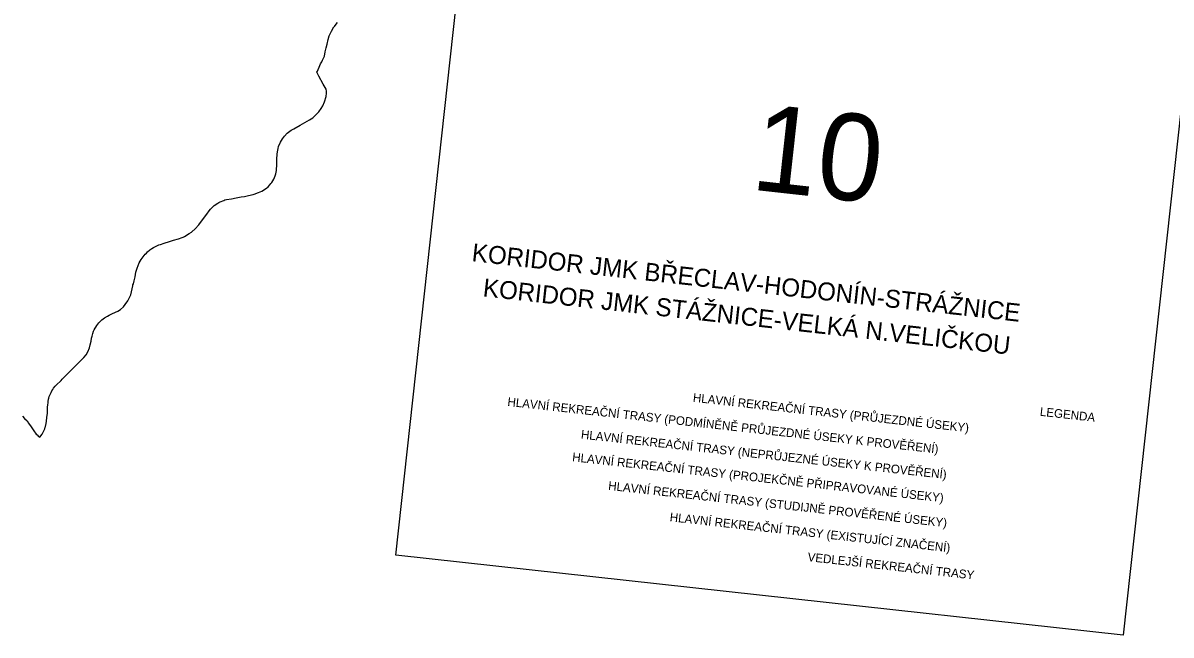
# Model space of a CAD drawing. Extents: x -678204 to -526855, y -1228851 to -1110393.
# Drawn here: x -574848 to -543059, y -1222170 to -1205218 of the extents above; entities that cross this region are included whole.
import ezdxf

# ---------------------------------------------------------------- set-up
doc = ezdxf.new("R2010")
doc.units = 0
for name, color, linetype in [('00_n_cyklo studie rekreacni hlavni', 7, 'Continuous'), ('00_n_cyklo trasovani rekreacni hlavni', 7, 'Continuous'), ('00_n_legenda popisy', 7, 'Continuous'), ('00_n_legenda popisy_hlavni', 7, 'Continuous'), ('_HELP BIG', 7, 'Continuous')]:
    doc.layers.add(name, color=color, linetype=linetype)

msp = doc.modelspace()

# ---------------------------------------------------------------- linework, layer by layer
at = {"layer": '00_n_cyklo studie rekreacni hlavni'}
for points in [[(-570414, -1211149), (-570379, -1211132), (-570249, -1211053), (-570181, -1211011), (-570068, -1210909), (-569987, -1210822), (-569975, -1210806), (-569934, -1210746), (-569868, -1210658), (-569817, -1210592), (-569761, -1210510), (-569696, -1210424), (-569656, -1210375), (-569575, -1210295), (-569550, -1210275), (-569454, -1210208), (-569427, -1210192), (-569384, -1210170), (-569287, -1210131), (-569256, -1210120), (-569211, -1210110), (-569076, -1210085), (-568947, -1210060), (-568802, -1210036), (-568711, -1210021), (-568637, -1210005), (-568518, -1209978), (-568471, -1209965), (-568448, -1209958), (-568322, -1209913), (-568233, -1209873), (-568106, -1209792), (-568059, -1209754), (-568008, -1209704), (-567985, -1209668), (-567959, -1209639), (-567901, -1209544), (-567861, -1209449), (-567846, -1209396), (-567829, -1209306), (-567819, -1209127), (-567814, -1208990), (-567807, -1208854), (-567801, -1208787), (-567786, -1208696), (-567770, -1208643), (-567718, -1208523), (-567665, -1208431), (-567602, -1208349), (-567528, -1208272), (-567420, -1208189), (-567349, -1208146), (-567175, -1208053), (-566910, -1207904), (-566824, -1207844), (-566744, -1207774), (-566657, -1207677), (-566593, -1207589), (-566549, -1207510), (-566499, -1207402), (-566457, -1207256), (-566441, -1207158), (-566440, -1207105), (-566457, -1207051), (-566533, -1206912), (-566652, -1206692), (-566709, -1206585), (-566693, -1206550), (-566632, -1206393), (-566612, -1206350), (-566574, -1206296), (-566551, -1206245), (-566503, -1206142), (-566478, -1206014), (-566454, -1205910), (-566427, -1205801), (-566395, -1205679), (-566370, -1205575), (-566355, -1205540), (-566303, -1205447), (-566243, -1205326)], [(-566151, -1205202), (-566243, -1205326)], [(-573761, -1215083), (-573705, -1215027), (-573631, -1214953), (-573484, -1214806), (-573344, -1214665), (-573267, -1214589), (-573163, -1214485), (-573098, -1214408), (-573048, -1214324), (-573005, -1214218), (-572983, -1214133), (-572964, -1214034), (-572946, -1213948), (-572931, -1213889), (-572913, -1213816), (-572891, -1213753), (-572874, -1213716), (-572805, -1213601), (-572743, -1213520), (-572663, -1213440), (-572586, -1213383), (-572508, -1213334), (-572460, -1213311), (-572371, -1213268), (-572223, -1213198), (-572145, -1213152), (-572060, -1213080), (-571972, -1212950), (-571964, -1212940), (-571947, -1212913), (-571905, -1212842), (-571863, -1212743), (-571845, -1212668), (-571828, -1212585), (-571809, -1212496), (-571805, -1212473), (-571786, -1212447), (-571765, -1212360), (-571744, -1212248), (-571720, -1212119), (-571690, -1212012), (-571661, -1211933), (-571628, -1211865), (-571575, -1211768), (-571464, -1211624), (-571429, -1211589), (-571396, -1211557), (-571332, -1211504), (-571277, -1211464), (-571233, -1211437), (-571158, -1211397), (-571086, -1211363), (-571044, -1211349), (-570938, -1211316), (-570790, -1211269), (-570681, -1211236), (-570541, -1211193), (-570444, -1211162), (-570414, -1211149)], [(-574862, -1216105), (-574808, -1216169), (-574734, -1216239), (-574692, -1216305), (-574622, -1216406), (-574548, -1216518), (-574485, -1216602), (-574453, -1216629), (-574422, -1216667), (-574385, -1216689), (-574320, -1216606), (-574266, -1216511), (-574246, -1216460), (-574230, -1216417), (-574223, -1216390), (-574204, -1216309), (-574198, -1216247), (-574186, -1216143), (-574173, -1216026), (-574170, -1215962), (-574164, -1215862), (-574159, -1215796), (-574154, -1215737), (-574149, -1215699), (-574140, -1215640), (-574132, -1215608), (-574118, -1215565), (-574095, -1215505), (-574069, -1215448), (-574047, -1215407), (-574022, -1215368), (-573998, -1215333), (-573956, -1215281), (-573930, -1215253), (-573794, -1215116), (-573761, -1215083)]]:
    msp.add_lwpolyline(points, dxfattribs=at)
at = {"layer": '00_n_cyklo trasovani rekreacni hlavni'}
for points in [[(-570414, -1211149), (-570379, -1211132), (-570249, -1211053), (-570181, -1211011), (-570068, -1210909), (-569987, -1210822), (-569975, -1210806), (-569934, -1210746), (-569868, -1210658), (-569817, -1210592), (-569761, -1210510), (-569696, -1210424), (-569656, -1210375), (-569575, -1210295), (-569550, -1210275), (-569454, -1210208), (-569427, -1210192), (-569384, -1210170), (-569287, -1210131), (-569256, -1210120), (-569211, -1210110), (-569076, -1210085), (-568947, -1210060), (-568802, -1210036), (-568711, -1210021), (-568637, -1210005), (-568518, -1209978), (-568471, -1209965), (-568448, -1209958), (-568322, -1209913), (-568233, -1209873), (-568106, -1209792), (-568059, -1209754), (-568008, -1209704), (-567985, -1209668), (-567959, -1209639), (-567901, -1209544), (-567861, -1209449), (-567846, -1209396), (-567829, -1209306), (-567819, -1209127), (-567814, -1208990), (-567807, -1208854), (-567801, -1208787), (-567786, -1208696), (-567770, -1208643), (-567718, -1208523), (-567665, -1208431), (-567602, -1208349), (-567528, -1208272), (-567420, -1208189), (-567349, -1208146), (-567175, -1208053), (-566910, -1207904), (-566824, -1207844), (-566744, -1207774), (-566657, -1207677), (-566593, -1207589), (-566549, -1207510), (-566499, -1207402), (-566457, -1207256), (-566441, -1207158), (-566440, -1207105), (-566457, -1207051), (-566533, -1206912), (-566652, -1206692), (-566709, -1206585), (-566693, -1206550), (-566632, -1206393), (-566612, -1206350), (-566574, -1206296), (-566551, -1206245), (-566503, -1206142), (-566478, -1206014), (-566454, -1205910), (-566427, -1205801), (-566395, -1205679), (-566370, -1205575), (-566355, -1205540), (-566303, -1205447), (-566243, -1205326)], [(-566151, -1205202), (-566243, -1205326)], [(-573761, -1215083), (-573705, -1215027), (-573631, -1214953), (-573484, -1214806), (-573344, -1214665), (-573267, -1214589), (-573163, -1214485), (-573098, -1214408), (-573048, -1214324), (-573005, -1214218), (-572983, -1214133), (-572964, -1214034), (-572946, -1213948), (-572931, -1213889), (-572913, -1213816), (-572891, -1213753), (-572874, -1213716), (-572805, -1213601), (-572743, -1213520), (-572663, -1213440), (-572586, -1213383), (-572508, -1213334), (-572460, -1213311), (-572371, -1213268), (-572223, -1213198), (-572145, -1213152), (-572060, -1213080), (-571972, -1212950), (-571964, -1212940), (-571947, -1212913), (-571905, -1212842), (-571863, -1212743), (-571845, -1212668), (-571828, -1212585), (-571809, -1212496), (-571805, -1212473), (-571786, -1212447), (-571765, -1212360), (-571744, -1212248), (-571720, -1212119), (-571690, -1212012), (-571661, -1211933), (-571628, -1211865), (-571575, -1211768), (-571464, -1211624), (-571429, -1211589), (-571396, -1211557), (-571332, -1211504), (-571277, -1211464), (-571233, -1211437), (-571158, -1211397), (-571086, -1211363), (-571044, -1211349), (-570938, -1211316), (-570790, -1211269), (-570681, -1211236), (-570541, -1211193), (-570444, -1211162), (-570414, -1211149)], [(-574862, -1216105), (-574808, -1216169), (-574734, -1216239), (-574692, -1216305), (-574622, -1216406), (-574548, -1216518), (-574485, -1216602), (-574453, -1216629), (-574422, -1216667), (-574385, -1216689), (-574320, -1216606), (-574266, -1216511), (-574246, -1216460), (-574230, -1216417), (-574223, -1216390), (-574204, -1216309), (-574198, -1216247), (-574186, -1216143), (-574173, -1216026), (-574170, -1215962), (-574164, -1215862), (-574159, -1215796), (-574154, -1215737), (-574149, -1215699), (-574140, -1215640), (-574132, -1215608), (-574118, -1215565), (-574095, -1215505), (-574069, -1215448), (-574047, -1215407), (-574022, -1215368), (-573998, -1215333), (-573956, -1215281), (-573930, -1215253), (-573794, -1215116), (-573761, -1215083)]]:
    msp.add_lwpolyline(points, dxfattribs=at)
at = {"layer": '_HELP BIG'}
msp.add_lwpolyline([(-564527, -1219958), (-561421, -1191670), (-541276, -1193882), (-544382, -1222170)], close=True, dxfattribs=at)

# ---------------------------------------------------------------- texts
at = {"layer": '00_n_legenda popisy'}
for s, p in [('HLAVNÍ REKREAČNÍ TRASY (PODMÍNĚNĚ PRŮJEZDNÉ ÚSEKY K PROVĚŘENÍ) ', (-561442, -1215821)), ('HLAVNÍ REKREAČNÍ TRASY (PRŮJEZDNÉ ÚSEKY) ', (-556307, -1215708)), ('LEGENDA', (-546700, -1216095)), ('HLAVNÍ REKREAČNÍ TRASY (NEPRŮJEZNÉ ÚSEKY K PROVĚŘENÍ) ', (-559407, -1216727)), ('HLAVNÍ REKREAČNÍ TRASY (PROJEKČNĚ PŘIPRAVOVANÉ ÚSEKY) ', (-559649, -1217355)), ('HLAVNÍ REKREAČNÍ TRASY (STUDIJNĚ PROVĚŘENÉ ÚSEKY) ', (-558652, -1218147)), ('HLAVNÍ REKREAČNÍ TRASY (EXISTUJÍCÍ ZNAČENÍ) ', (-556948, -1219017)), ('VEDLEJŠÍ REKREAČNÍ TRASY ', (-553131, -1220121))]:
    msp.add_text(s, height=240, rotation=353.6836, dxfattribs=at).set_placement(p)
at = {"layer": '00_n_legenda popisy_hlavni'}
for s, p in [('KORIDOR JMK BŘECLAV-HODONÍN-STRÁŽNICE', (-562437, -1211815)), ('KORIDOR JMK STÁŽNICE-VELKÁ N.VELIČKOU', (-562129, -1212787))]:
    msp.add_text(s, height=497.66, rotation=353.6836, dxfattribs=at).set_placement(p)
at = {"layer": '_HELP BIG'}
msp.add_text('10', height=2400, rotation=353.6836, dxfattribs=at).set_placement((-554729, -1209827))

doc.saveas('drawing.dxf')
